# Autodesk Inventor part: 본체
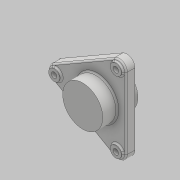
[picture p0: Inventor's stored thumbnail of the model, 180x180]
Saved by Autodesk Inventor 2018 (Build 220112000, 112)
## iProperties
Created: 2023-04
Part Number: 본체
Material: 일반
Document SubType Name: Modeling
Designer: home
Density: 1 g/cm^3
Appearance: 기본값
Author: home
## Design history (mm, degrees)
sketch "스케치1"
  geometry: L1 (82, 0)-(0, 0); L2 (0, 0)-(-40.998, 71.01); L3 (0, 0)-(-40.998, -71.018); L4 (90, 13.857)-(-32.998, 84.866); L5 (-56.998, 71.01)-(-56.998, -71.018); L6 (90, -13.856)-(-32.997, -84.874); A1 r 16 centre (82, 0) between (90, -13.856) and (90, 13.857); A2 r 16 centre (-40.998, 71.01) between (-32.998, 84.866) and (-56.998, 71.01); A3 r 16 centre (-40.998, -71.018) between (-56.998, -71.018) and (-32.997, -84.874); 1 further point
  constraints: 12 end point, 6 point on circle, 6 tangent, 3 centre point, 3 coincident, 1 horizontal, 1 vertical
  dimensions: "d3" = 16 radius of A1; "d4" = 16 radius of A2; "d5" = 16 radius of A3
extrude "돌출1" new body sketch "스케치1" distance "d6" = 18; taper "d7" = 0 deg
sketch "스케치2"
  geometry: C1 r 40 at (0, 0); 1 further point
  constraints: 1 centre point
  dimensions: "d9" = 80 diameter of C1
extrude "돌출2" join sketch "스케치2" distance "d10" = 23; taper "d12" = 0 deg; dims "d11" = 47, "d13" = 0
sketch "스케치3"
  geometry: C1 r 45 at (0, 0); 1 further point
  constraints: 1 centre point, 1 coincident
  dimensions: "d14" = 90 diameter of C1
extrude "돌출3" join sketch "스케치3" distance "d15" = 5; taper "d16" = 0 deg
fillet "모깎기1" dims "d17" = 3
sketch "스케치4"
  geometry: C1 r 11 at (40.998, 71.01); C2 r 11 at (40.998, -71.018); C3 r 11 at (-82, 0); A1 r 16 centre (40.998, 71.01) between (56.998, 71.01) and (32.998, 84.866) reference; A2 r 16 centre (40.998, -71.018) between (32.997, -84.874) and (56.998, -71.018) reference; A3 r 16 centre (-82, 0) between (-90, 13.857) and (-90, -13.856) reference; 1 further point
  constraints: 3 centre point, 3 coincident
  dimensions: "d18" = 22 diameter of C1; "d19" = 22 diameter of C2; "d20" = 22 diameter of C3
extrude "돌출4" join sketch "스케치4" distance "d21" = 4; taper "d22" = 0 deg
fillet "모깎기2" dims "d23" = 3
hole "구멍1" diameter "d26" = 11; stored, may be unused: countersink angle "d30" = 90 deg, drill point angle "d32" = 118 deg; dims "d24" = 10, "d25" = 10, "d27" = 6, "d28" = 4, "d29" = 2, "d31" = 30
hole "구멍2" diameter "d35" = 11; stored, may be unused: countersink angle "d39" = 90 deg, drill point angle "d41" = 118 deg; dims "d33" = 10, "d34" = 10, "d36" = 6, "d37" = 4, "d38" = 2, "d40" = 30
hole "구멍3" diameter "d44" = 11; stored, may be unused: countersink angle "d48" = 90 deg, drill point angle "d50" = 118 deg; dims "d42" = 10, "d43" = 10, "d45" = 6, "d46" = 4, "d47" = 2, "d49" = 30
node "솔리드1"
